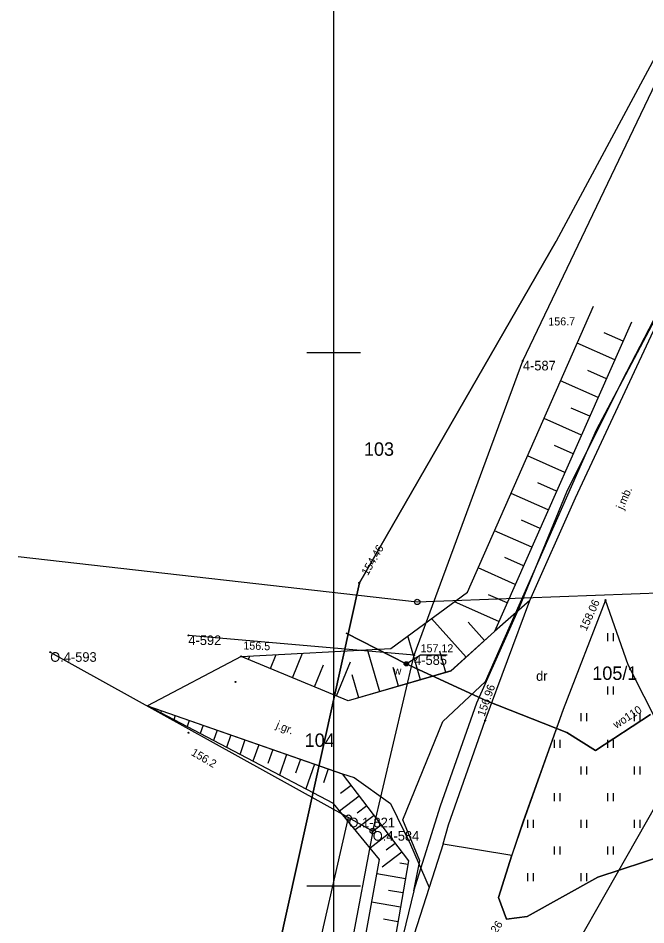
# Model space of a CAD drawing. Extents: x 5598798 to 5599616, y 5661498 to 5662453.
# Drawn here: x 5599170.4 to 5599229.2, y 5662046.3 to 5662131.3 of the extents above; entities that cross this region are included whole.
import ezdxf

# ---------------------------------------------------------------- set-up
doc = ezdxf.new("R2010")
doc.units = 0
for name, color, linetype in [('BUBZ_L_1', 7, 'Continuous'), ('Dzialki', 7, 'Continuous'), ('KTJZ_E_T_0', 7, 'Continuous'), ('KTJZ_L_0', 7, 'Continuous'), ('KTKR_L_0', 7, 'Continuous'), ('Numery_dzialek', 7, 'Continuous'), ('Numery_punktow', 7, 'Continuous'), ('Numery_uzytkow', 7, 'Continuous'), ('Podzial_sekcyjny_krzyze', 7, 'Continuous'), ('Podzial_sekcyjny_podstawowy', 7, 'Continuous'), ('PTTU_L_2', 7, 'Continuous'), ('Punkty', 7, 'Continuous'), ('RTPW_T_0', 7, 'Continuous'), ('RTPW_T_1', 7, 'Continuous'), ('SUOW_L_0', 7, 'Continuous'), ('SUPE_L_3', 7, 'Continuous'), ('SUPT_L_0', 7, 'Continuous'), ('SUPW_E_T_0', 7, 'Continuous'), ('SUPW_L_0', 7, 'Continuous'), ('SUSM_T_3', 7, 'Continuous'), ('SUTW_T_0', 7, 'Continuous'), ('SUUW_E_T_5', 7, 'Continuous'), ('SUUW_T_7', 7, 'Continuous'), ('Uzytki', 7, 'Continuous')]:
    doc.layers.add(name, color=color, linetype=linetype)

# ---------------------------------------------------------------- blocks, each defined once
blk = doc.blocks.new('GRO')
blk.add_circle((0, 0), 0.045)
blk = doc.blocks.new('GRT')
blk.add_circle((0, 0), 0.25)
blk = doc.blocks.new('POINT_DISPLAY')
blk.add_line((0, 0), (0, 0))
blk = doc.blocks.new('2_PTTU04')
for p, q in [((-0.2625, -0.375), (-0.2625, 0.375)), ((0.2625, -0.375), (0.2625, 0.375))]:
    blk.add_line(p, q)
blk = doc.blocks.new('2_RTPW01')
blk.add_circle((0, 0), 0.045)
blk = doc.blocks.new('2_RTPW02')
blk.add_circle((0, 0), 0.045)
blk = doc.blocks.new('4_SUSM04_01')
blk.add_circle((0, 0), 0.25)
blk = doc.blocks.new('4_SUPS01_08')
blk.add_circle((0, 0), 0.0625)
blk = doc.blocks.new('4_SUUS25')
for radius in [0.2, 0.175, 0.15, 0.125, 0.1, 0.075, 0.05, 0.025, 0.00715]:
    blk.add_circle((0, 0), radius)

msp = doc.modelspace()

# ---------------------------------------------------------------- linework, layer by layer
at = {"layer": 'BUBZ_L_1'}
for p, q in [((5599212.523258, 5662077.514278), (5599224.339158, 5662104.34536)), ((5599227.895357, 5662102.825434), (5599215.048152, 5662073.829903)), ((5599227.112098, 5662101.057657), (5599225.346261, 5662101.840056)), ((5599226.329699, 5662099.291819), (5599222.802005, 5662100.854854)), ((5599225.548182, 5662097.527972), (5599223.786323, 5662098.308608)), ((5599224.767546, 5662095.766113), (5599221.2478, 5662097.325626)), ((5599223.987789, 5662094.006241), (5599222.2299, 5662094.785118)), ((5599223.208912, 5662092.248351), (5599219.697097, 5662093.80435)), ((5599222.430913, 5662090.492444), (5599220.676984, 5662091.269566)), ((5599221.65379, 5662088.738515), (5599218.149888, 5662090.291008)), ((5599220.877544, 5662086.986564), (5599219.127567, 5662087.761935)), ((5599220.102173, 5662085.236587), (5599216.606164, 5662086.785582)), ((5599219.327675, 5662083.488583), (5599217.581641, 5662084.262208)), ((5599218.554051, 5662081.742549), (5599215.065919, 5662083.288054)), ((5599217.781298, 5662079.998484), (5599216.039199, 5662080.770365)), ((5599217.009417, 5662078.256384), (5599213.529145, 5662079.798407)), ((5599205.34931, 5662072.258822), (5599212.523258, 5662077.514278)), ((5599216.238406, 5662076.516248), (5599214.500231, 5662077.28639)), ((5599215.468263, 5662074.778074), (5599211.305766, 5662076.622374)), ((5599212.418629, 5662071.447719), (5599209.156868, 5662075.048144)), ((5599214.129691, 5662072.997834), (5599212.579575, 5662074.708897)), ((5599215.048152, 5662073.829903), (5599210.970184, 5662070.135518)), ((5599208.141653, 5662069.310772), (5599206.941878, 5662073.425498)), ((5599191.339991, 5662071.500198), (5599205.34931, 5662072.258822)), ((5599204.318306, 5662068.195958), (5599203.168093, 5662072.140706)), ((5599210.514505, 5662070.00265), (5599209.93713, 5662071.982802)), ((5599201.369297, 5662067.336083), (5599191.339991, 5662071.500198)), ((5599192.011435, 5662071.221417), (5599192.145289, 5662071.543806)), ((5599194.070916, 5662070.366332), (5599194.615331, 5662071.677562)), ((5599196.130396, 5662069.511247), (5599197.085373, 5662071.811318)), ((5599198.189876, 5662068.656162), (5599199.044962, 5662070.715642)), ((5599200.249357, 5662067.801076), (5599201.569643, 5662070.980996)), ((5599206.08429, 5662068.710885), (5599205.569363, 5662070.47687)), ((5599210.970184, 5662070.135518), (5599201.369297, 5662067.336083)), ((5599202.345932, 5662067.620851), (5599201.721718, 5662069.761643)), ((5599199.976393, 5662057.714184), (5599182.559792, 5662066.87034)), ((5599182.559792, 5662066.87034), (5599200.805755, 5662060.50084)), ((5599183.862715, 5662066.415502), (5599183.794837, 5662066.22106)), ((5599185.165637, 5662065.960664), (5599185.029881, 5662065.571779)), ((5599186.468559, 5662065.505825), (5599186.264925, 5662064.922499)), ((5599187.771482, 5662065.050987), (5599187.49997, 5662064.273218)), ((5599189.074404, 5662064.596148), (5599188.735014, 5662063.623938)), ((5599190.377326, 5662064.14131), (5599189.970058, 5662062.974657)), ((5599191.680249, 5662063.686472), (5599191.22541, 5662062.383549)), ((5599192.983171, 5662063.231633), (5599192.440147, 5662061.676096)), ((5599194.286093, 5662062.776795), (5599193.831255, 5662061.473873)), ((5599195.589016, 5662062.321957), (5599194.910236, 5662060.377536)), ((5599196.891938, 5662061.867118), (5599196.4371, 5662060.564196)), ((5599198.19486, 5662061.41228), (5599197.380325, 5662059.078975)), ((5599199.497783, 5662060.957442), (5599199.042944, 5662059.654519)), ((5599200.800705, 5662060.502603), (5599200.79485, 5662060.485831)), ((5599200.805755, 5662060.50084), (5599207.009383, 5662052.339919)), ((5599201.637665, 5662059.406457), (5599200.640047, 5662058.648105)), ((5599202.396016, 5662058.408839), (5599200.555803, 5662057.009978)), ((5599204.289076, 5662052.472617), (5599199.976393, 5662057.714184)), ((5599203.095447, 5662057.488733), (5599202.193064, 5662056.802775)), ((5599203.781404, 5662056.58635), (5599202.011405, 5662055.240863)), ((5599204.454148, 5662055.70135), (5599203.586196, 5662055.041566)), ((5599205.113933, 5662054.833398), (5599203.411467, 5662053.539248)), ((5599205.761008, 5662053.982166), (5599204.926173, 5662053.347555)), ((5599201.547205, 5662037.521709), (5599204.289076, 5662052.472617)), ((5599207.009383, 5662052.339919), (5599203.009868, 5662029.29958)), ((5599206.395619, 5662053.14733), (5599204.542611, 5662051.738743)), ((5599206.951015, 5662052.003673), (5599206.179332, 5662052.137628)), ((5599206.719187, 5662050.668162), (5599204.043338, 5662051.132656)), ((5599206.48694, 5662049.330237), (5599205.142659, 5662049.563588)), ((5599206.253589, 5662047.985957), (5599203.552255, 5662048.454875)), ((5599206.01913, 5662046.63529), (5599204.662047, 5662046.870862))]:
    msp.add_line(p, q, dxfattribs=at)
at = {"layer": 'Dzialki'}
for p, q in [((5599217.72, 5662099.21), (5599239.49, 5662144.83)), ((5599207.53, 5662071.61), (5599217.72, 5662099.21)), ((5599241.09, 5662076.83), (5599221.18, 5662041.76)), ((5599207.53, 5662071.61), (5599186.39, 5662073.47)), ((5599173.45, 5662071.9), (5599201.39, 5662056.39)), ((5599203.66, 5662055.13), (5599207.53, 5662071.61)), ((5599188.89, 5662001.71), (5599201.39, 5662056.39)), ((5599201.39, 5662056.39), (5599203.66, 5662055.13)), ((5599203.66, 5662055.13), (5599201.18, 5662042.06))]:
    msp.add_line(p, q, dxfattribs=at)
at = {"layer": 'KTJZ_L_0'}
for p, q in [((5599222.646593, 5662086.37844), (5599229.944352, 5662102.03161)), ((5599218.363434, 5662076.746595), (5599222.646593, 5662086.37844)), ((5599214.187322, 5662065.486414), (5599218.363434, 5662076.746595)), ((5599214.19, 5662065.49), (5599218.36, 5662076.75)), ((5599218.36, 5662076.75), (5599215.05, 5662073.83)), ((5599225.455818, 5662076.787741), (5599221.476965, 5662066.532515)), ((5599227.58506, 5662070.703245), (5599225.455818, 5662076.787741)), ((5599215.05, 5662073.83), (5599210.97, 5662070.14)), ((5599191.34, 5662071.5), (5599182.56, 5662066.87)), ((5599201.37, 5662067.34), (5599191.34, 5662071.5)), ((5599230.59085, 5662064.788744), (5599227.58506, 5662070.703245)), ((5599210.97, 5662070.14), (5599201.37, 5662067.34)), ((5599182.56, 5662066.87), (5599200.81, 5662060.5)), ((5599221.476965, 5662066.532515), (5599217.762872, 5662056.073208)), ((5599210.747758, 5662055.713668), (5599214.187322, 5662065.486414)), ((5599210.75, 5662055.71), (5599214.19, 5662065.49)), ((5599200.81, 5662060.5), (5599201.92, 5662060.15)), ((5599201.92, 5662060.15), (5599205.32, 5662057.71)), ((5599205.32, 5662057.71), (5599207.19, 5662053.89)), ((5599217.762872, 5662056.073208), (5599216.67, 5662052.87)), ((5599210.24, 5662053.93), (5599210.747758, 5662055.713668)), ((5599210.24, 5662053.93), (5599210.75, 5662055.71)), ((5599207.19, 5662053.89), (5599208.94, 5662049.84)), ((5599210.24, 5662053.93), (5599208.94, 5662049.84)), ((5599210.24, 5662053.93), (5599216.67, 5662052.87)), ((5599232.86, 5662053.51), (5599224.74, 5662050.8)), ((5599215.45, 5662048.9), (5599216.67, 5662052.87)), ((5599224.74, 5662050.8), (5599218.12, 5662047.13)), ((5599208.94, 5662049.84), (5599207.24, 5662044.5)), ((5599216.19, 5662046.89), (5599215.45, 5662048.9)), ((5599218.12, 5662047.13), (5599216.19, 5662046.89))]:
    msp.add_line(p, q, dxfattribs=at)
at = {"layer": 'KTKR_L_0'}
for p, q in [((5599225.46, 5662076.79), (5599221.48, 5662066.53)), ((5599227.59, 5662070.7), (5599225.46, 5662076.79)), ((5599230.59, 5662064.79), (5599227.59, 5662070.7)), ((5599221.48, 5662066.53), (5599217.76, 5662056.07)), ((5599217.76, 5662056.07), (5599216.67, 5662052.87)), ((5599224.74, 5662050.8), (5599232.86, 5662053.51)), ((5599216.67, 5662052.87), (5599215.45, 5662048.9)), ((5599218.12, 5662047.13), (5599224.74, 5662050.8)), ((5599215.45, 5662048.9), (5599216.19, 5662046.89)), ((5599216.19, 5662046.89), (5599218.12, 5662047.13))]:
    msp.add_line(p, q, dxfattribs=at)
at = {"layer": 'Podzial_sekcyjny_krzyze'}
for p, q in [((5599200, 5662097.5), (5599200, 5662102.5)), ((5599197.5, 5662100), (5599202.5, 5662100)), ((5599200, 5662047.5), (5599200, 5662052.5)), ((5599197.5, 5662050), (5599202.5, 5662050))]:
    msp.add_line(p, q, dxfattribs=at)
at = {"layer": 'Podzial_sekcyjny_podstawowy'}
msp.add_line((5599200, 5662000), (5599200, 5662250), dxfattribs=at)
at = {"layer": 'PTTU_L_2'}
for p, q in [((5599225.46, 5662076.79), (5599221.48, 5662066.53)), ((5599227.59, 5662070.7), (5599225.46, 5662076.79)), ((5599230.59, 5662064.79), (5599227.59, 5662070.7)), ((5599221.48, 5662066.53), (5599217.76, 5662056.07)), ((5599217.76, 5662056.07), (5599216.67, 5662052.87)), ((5599224.74, 5662050.8), (5599232.86, 5662053.51)), ((5599216.67, 5662052.87), (5599215.45, 5662048.9)), ((5599218.12, 5662047.13), (5599224.74, 5662050.8)), ((5599215.45, 5662048.9), (5599216.19, 5662046.89)), ((5599216.19, 5662046.89), (5599218.12, 5662047.13))]:
    msp.add_line(p, q, dxfattribs=at)
at = {"layer": 'SUOW_L_0'}
msp.add_line((5599214.305035, 5662067.349967), (5599221.836502, 5662064.359659), dxfattribs=at)
msp.add_line((5599214.305035, 5662067.349967), (5599221.836502, 5662064.359659), dxfattribs=at)
at = {"layer": 'SUPE_L_3'}
for p, q in [((5599170.447324, 5662080.869967), (5599207.821671, 5662076.607039)), ((5599207.821671, 5662076.607039), (5599244.04787, 5662077.960672))]:
    msp.add_line(p, q, dxfattribs=at)
at = {"layer": 'SUPT_L_0'}
for p, q in [((5599224.612833, 5662092.746111), (5599234.454092, 5662111.378469)), ((5599227.058149, 5662097.403859), (5599232.318985, 5662107.598181)), ((5599221.823903, 5662086.920005), (5599227.058149, 5662097.403859)), ((5599214.213895, 5662069.158749), (5599224.612833, 5662092.746111)), ((5599217.387347, 5662076.114122), (5599221.823903, 5662086.920005)), ((5599213.419397, 5662067.139748), (5599217.387347, 5662076.114122)), ((5599210.217287, 5662065.406184), (5599214.213895, 5662069.158749)), ((5599210.007104, 5662057.487678), (5599213.419397, 5662067.139748)), ((5599206.475235, 5662056.176823), (5599210.217287, 5662065.406184)), ((5599207.516805, 5662049.527352), (5599210.007104, 5662057.487678)), ((5599208.052903, 5662052.350861), (5599206.475235, 5662056.176823)), ((5599207.516805, 5662049.527352), (5599208.052903, 5662052.350861)), ((5599207.516805, 5662049.527352), (5599202.357147, 5662028.280122))]:
    msp.add_line(p, q, dxfattribs=at)
at = {"layer": 'SUPW_L_0'}
for p, q in [((5599246.158544, 5662157.63618), (5599220.8293, 5662110.428489)), ((5599202.403352, 5662078.401046), (5599220.8293, 5662110.428489)), ((5599220.8293, 5662110.428489), (5599202.403352, 5662078.401046)), ((5599193.556349, 5662038.364661), (5599202.403352, 5662078.401046)), ((5599202.403352, 5662078.401046), (5599193.556349, 5662038.364661)), ((5599206.792883, 5662070.810935), (5599201.175187, 5662073.67466)), ((5599201.175187, 5662073.67466), (5599206.792883, 5662070.810935)), ((5599214.305035, 5662067.349967), (5599206.792883, 5662070.810935)), ((5599206.792883, 5662070.810935), (5599214.305035, 5662067.349967)), ((5599221.836502, 5662064.359659), (5599214.305035, 5662067.349967)), ((5599214.305035, 5662067.349967), (5599221.836502, 5662064.359659)), ((5599229.661799, 5662066.048231), (5599224.505699, 5662062.689511)), ((5599224.505699, 5662062.689511), (5599229.661799, 5662066.048231)), ((5599224.505699, 5662062.689511), (5599221.836502, 5662064.359659)), ((5599221.836502, 5662064.359659), (5599224.505699, 5662062.689511))]:
    msp.add_line(p, q, dxfattribs=at)
at = {"layer": 'SUTW_T_0'}
for p, q in [((5599206.792883, 5662070.810935), (5599208.136217, 5662071.643104)), ((5599208.136217, 5662071.643104), (5599210.633342, 5662071.643104))]:
    msp.add_line(p, q, dxfattribs=at)
at = {"layer": 'Uzytki'}
for p, q in [((5599188.89, 5662001.71), (5599201.39, 5662056.39)), ((5599201.39, 5662056.39), (5599203.66, 5662055.13)), ((5599203.66, 5662055.13), (5599201.18, 5662042.06))]:
    msp.add_line(p, q, dxfattribs=at)

# ---------------------------------------------------------------- block references
at = {"layer": 'BUBZ_L_1'}
for p in [(5599227.895357, 5662102.825434), (5599182.559792, 5662066.87034)]:
    msp.add_blockref('POINT_DISPLAY', p, dxfattribs=at)
at = {"layer": 'PTTU_L_2'}
for p in [(5599225.94, 5662073.31), (5599225.94, 5662068.31), (5599223.44, 5662065.81), (5599228.44, 5662065.81), (5599220.94, 5662063.31), (5599225.94, 5662063.31), (5599223.44, 5662060.81), (5599228.44, 5662060.81), (5599220.94, 5662058.31), (5599225.94, 5662058.31), (5599218.44, 5662055.81), (5599223.44, 5662055.81), (5599228.44, 5662055.81), (5599220.94, 5662053.31), (5599225.94, 5662053.31), (5599218.44, 5662050.81), (5599223.44, 5662050.81)]:
    msp.add_blockref('2_PTTU04', p, dxfattribs=at)
at = {"layer": 'Punkty'}
for name, p in [('GRO', (5599217.72, 5662099.21)), ('GRO', (5599186.39, 5662073.47)), ('GRO', (5599173.45, 5662071.9)), ('GRO', (5599207.53, 5662071.61)), ('GRT', (5599201.39, 5662056.39)), ('GRT', (5599203.66, 5662055.13))]:
    msp.add_blockref(name, p, dxfattribs=at)
at = {"layer": 'RTPW_T_0'}
for p in [(5599191.339991, 5662071.500198), (5599190.793891, 5662069.116668), (5599186.410633, 5662064.350513)]:
    msp.add_blockref('2_RTPW01', p, dxfattribs=at)
at = {"layer": 'RTPW_T_1'}
for p in [(5599225.455818, 5662076.787741), (5599214.187322, 5662065.486414)]:
    msp.add_blockref('2_RTPW02', p, dxfattribs=at)
at = {"layer": 'SUSM_T_3'}
msp.add_blockref('4_SUSM04_01', (5599207.821671, 5662076.607039), dxfattribs=at)
at = {"layer": 'SUTW_T_0'}
for p in [(5599202.403352, 5662078.401046), (5599206.792883, 5662070.810935)]:
    msp.add_blockref('4_SUPS01_08', p, dxfattribs=at)
at = {"layer": 'SUUW_T_7'}
msp.add_blockref('4_SUUS25', (5599206.792883, 5662070.810935), dxfattribs=at)

# ---------------------------------------------------------------- texts
at = {"layer": 'KTJZ_E_T_0'}
for s, rotation, p in [('j.mb.', 66.370632, (5599227.106972, 5662085.207728)), ('j.gr.', 337.8, (5599194.534473, 5662064.806192))]:
    msp.add_text(s, height=0.75, rotation=rotation, dxfattribs=at).set_placement(p)
at = {"layer": 'Numery_dzialek'}
for s, p in [('103', (5599202.836741, 5662090.307839)), ('105/1', (5599224.222055, 5662069.301333)), ('104', (5599197.282532, 5662063.021242))]:
    msp.add_text(s, height=1.26, dxfattribs=at).set_placement(p)
at = {"layer": 'Numery_punktow'}
for s, p in [('4-587', (5599217.72, 5662098.31)), ('4-592', (5599186.39, 5662072.57)), ('O.4-593', (5599173.45, 5662071)), ('4-585', (5599207.53, 5662070.71)), ('O.1-821', (5599201.39, 5662055.49)), ('O.4-584', (5599203.66, 5662054.23))]:
    msp.add_text(s, height=0.9, dxfattribs=at).set_placement(p)
at = {"layer": 'Numery_uzytkow'}
msp.add_text('dr', height=0.9, dxfattribs=at).set_placement((5599218.958483, 5662069.220578))
at = {"layer": 'RTPW_T_0'}
for s, rotation, p in [('156.7', 0.707324, (5599220.105627, 5662102.514491)), ('156.5', 358.066699, (5599191.529162, 5662072.161352)), ('156.2', 329.780303, (5599186.576505, 5662062.293695))]:
    msp.add_text(s, height=0.75, rotation=rotation, dxfattribs=at).set_placement(p)
at = {"layer": 'RTPW_T_1'}
for s, rotation, p in [('158.06', 65.308428, (5599223.663124, 5662073.832416)), ('156.96', 70.643079, (5599214.126007, 5662065.821524)), ('157.26', 55.741983, (5599214.148144, 5662043.869749))]:
    msp.add_text(s, height=0.75, rotation=rotation, dxfattribs=at).set_placement(p)
at = {"layer": 'SUPW_E_T_0'}
msp.add_text('wo110', height=0.75, rotation=33.080509, dxfattribs=at).set_placement((5599226.462211, 5662064.705241))
at = {"layer": 'SUTW_T_0'}
msp.add_text('154.46', height=0.75, rotation=60.087432, dxfattribs=at).set_placement((5599203.196208, 5662079.027176))
msp.add_text('157.12', height=0.75, dxfattribs=at).set_placement((5599208.136217, 5662071.893104))
at = {"layer": 'SUUW_E_T_5'}
msp.add_text('w', height=0.75, dxfattribs=at).set_placement((5599205.616649, 5662069.790353))

doc.saveas('drawing.dxf')
